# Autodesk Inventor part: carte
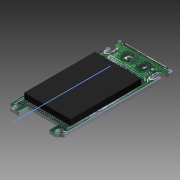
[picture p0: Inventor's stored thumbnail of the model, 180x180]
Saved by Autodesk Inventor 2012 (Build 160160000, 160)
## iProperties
Created: 2013-04
Part Number: carte
Material: Default
Document SubType Name: Modeling
Designer: hilarion
Density: 1 g/cm^3
Author: hilarion
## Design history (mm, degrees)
sketch "Esquisse1"
  geometry: L1 (-43.6, 52.9)-(31.4, 52.9); L2 (31.4, 52.9)-(31.4, -80.143); L3 (31.4, -80.143)-(-43.6, -80.143); L4 (-43.6, -80.143)-(-43.6, 52.9); L5 (-12.365, 3.755)-(0.905, 3.755); L6 (-1.794, -24.745)-(-1.794, -22.442); L7 (-1.994, -22.242)-(-9.292, -22.242); L8 (-9.492, -22.442)-(-9.492, -24.745); L9 (-11.565, 2.035)-(-11.383, 2.035); L10 (-11.183, 1.835)-(-11.183, 0.788); L11 (0.105, 2.125)-(-0.055, 2.125); L12 (-0.255, 1.925)-(-0.255, 0.788); L13 (0.445, 0.788)-(0.905, 0.788); L14 (-12.518, 2.035)-(-12.565, 2.035); L15 (-12.518, 0.788)-(-12.565, 0.788); L16 (-12.565, -23.863)-(-12.565, 0.588); L17 (-12.565, 3.035)-(-12.565, 3.555); L18 (1.105, 3.555)-(1.105, 3.125); L19 (1.105, 0.588)-(1.105, -23.863); L20 (0.205, -24.945)-(-1.594, -24.945); L21 (-9.692, -24.945)-(-11.665, -24.945); L22 (-11.713, 0.36)-(-11.713, 0.588); L23 (-11.213, 0.36)-(-11.213, 0.788); L24 (-11.183, 0.788)-(-11.213, 0.788); L25 (-11.913, 0.788)-(-12.365, 0.788); L26 (-0.255, 0.356)-(-0.255, 0.788); L27 (0.245, 0.356)-(0.245, 0.588); C1 r 0.5 at (-10.944, -23.45); C2 r 0.5 at (-0.255, -23.351); A1 r 0.9 centre (-12.565, -24.945) between (-11.665, -24.945) and (-12.402, -24.06); A2 r 0.9 centre (1.105, -24.945) between (0.941, -24.06) and (0.205, -24.945); A3 r 0.25 centre (-11.463, 0.36) between (-11.713, 0.36) and (-11.213, 0.36); A4 r 0.25 centre (-0.005, 0.356) between (-0.255, 0.356) and (0.245, 0.356); A5 r 1 centre (0.105, 3.125) between (0.105, 2.125) and (1.105, 3.125); A6 r 1 centre (-11.565, 3.035) between (-12.565, 3.035) and (-11.565, 2.035); A7 r 0.2 centre (0.905, 0.588) between (1.105, 0.588) and (0.905, 0.788); A8 r 0.2 centre (0.905, 3.555) between (1.105, 3.555) and (0.905, 3.755); A9 r 0.2 centre (-12.365, 3.555) between (-12.365, 3.755) and (-12.565, 3.555); A10 r 0.2 centre (-12.365, 0.588) between (-12.365, 0.788) and (-12.565, 0.588); A11 r 0.2 centre (-11.383, 1.835) between (-11.183, 1.835) and (-11.383, 2.035); A12 r 0.2 centre (-11.913, 0.588) between (-11.713, 0.588) and (-11.913, 0.788); A13 r 0.2 centre (-0.055, 1.925) between (-0.055, 2.125) and (-0.255, 1.925); A14 r 0.2 centre (0.445, 0.588) between (0.445, 0.788) and (0.245, 0.588); A15 r 0.2 centre (-1.594, -24.745) between (-1.794, -24.745) and (-1.594, -24.945); A16 r 0.2 centre (-1.994, -22.442) between (-1.794, -22.442) and (-1.994, -22.242); A17 r 0.2 centre (-9.292, -22.442) between (-9.292, -22.242) and (-9.492, -22.442); A18 r 0.2 centre (-9.692, -24.745) between (-9.692, -24.945) and (-9.492, -24.745); A19 r 0.2 centre (-12.365, -23.863) between (-12.565, -23.863) and (-12.402, -24.06); A20 r 0.2 centre (0.905, -23.863) between (0.941, -24.06) and (1.105, -23.863); 3 further points; 1 other entity
  constraints: 46 end point, 42 point on circle, 36 tangent, 22 centre point, 13 equal radius, 12 parallel, 11 perpendicular, 6 point on line, 3 horizontal, 2 other
  dimensions: "d53" = 31.4 horizontal distance of L1.end point (0, 0); "d54" = 75 distance of L1.start L1.end; "d55" = 52.9 vertical distance of L1.end point (0, 0); "d59" = 1.8 diameter of A1; "d60" = 1.8 diameter of A2; "d61" = 0.5 diameter of A3; "d64" = 0.5 diameter of A4; "d68" = 1 radius of A5; "d71" = 0.2 radius of A7; "d76" = 0.2 radius of A11; "d84" = 1 diameter of C1; "d85" = 1 diameter of C2
extrude "Extrusion1" new body sketch "Esquisse1" distance "d86" = 0.75; taper "d87" = 0 deg
sketch "Esquisse2"
  geometry: L1 (-43.679, 52.154)-(31.071, 52.154); L2 (31.071, 52.154)-(31.071, -80.446); L3 (31.071, -80.446)-(-43.679, -80.446); L4 (-43.679, -80.446)-(-43.679, 52.154); 1 further point; 1 other entity
  constraints: 2 other
feature "Décalcomanie1" sketch "Esquisse2"
sketch "Esquisse3"
  geometry: L1 (-23.052, 45.072)-(41.67, 43.543); L2 (41.67, 43.543)-(38.958, -71.267); L3 (38.958, -71.267)-(-25.764, -69.739); L4 (-25.764, -69.739)-(-23.052, 45.072); 1 further point; 1 other entity
  constraints: 2 other
feature "Décalcomanie2" sketch "Esquisse3"
sketch "Esquisse4"
  geometry: L1 (2.716, -10.133)-(8.745, -10.133); L2 (8.945, -10.333)-(8.945, -16.53); L3 (8.745, -16.73)-(2.716, -16.73); L4 (2.516, -16.53)-(2.516, -10.333); A1 r 0.2 centre (2.716, -16.53) between (2.516, -16.53) and (2.716, -16.73); A2 r 0.2 centre (8.745, -16.53) between (8.745, -16.73) and (8.945, -16.53); A3 r 0.2 centre (8.745, -10.333) between (8.945, -10.333) and (8.745, -10.133); A4 r 0.2 centre (2.716, -10.333) between (2.716, -10.133) and (2.516, -10.333); 1 further point
  constraints: 8 end point, 8 point on circle, 8 tangent, 4 centre point, 3 equal radius, 2 parallel, 1 horizontal, 1 perpendicular
  dimensions: "d125" = 0.2 radius of A1
extrude "Extrusion2" join sketch "Esquisse4" distance "d126" = 1.4; taper "d127" = 0 deg
chamfer "Chanfrein1" distance "d128" = 0.2; stored, may be unused: second distance "d129" = 2, angle "d130" = 45 deg
sketch "Esquisse5"
  geometry: L1 (-11.713, -21.272)-(0, -21.272); L2 (0, -21.272)-(0, -3.347); L3 (0, -3.347)-(-11.713, -3.347); L4 (-11.713, -3.347)-(-11.713, -21.272); 1 further point
  constraints: 8 end point, 2 parallel, 1 horizontal, 1 perpendicular
extrude "Extrusion3" join sketch "Esquisse5" distance "d131" = 1.4; taper "d132" = 0 deg
node "Solide1"
node "Image1"
node "Image2"
node "Image3"
